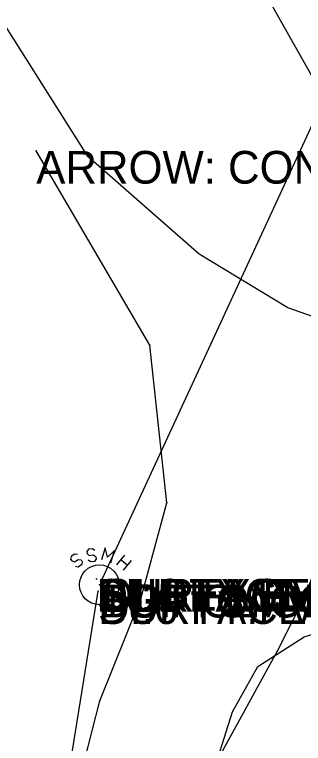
# Model space of a CAD drawing. Extents: x 997398 to 1003416, y 334596 to 337085.
# Drawn here: x 999242.3 to 999286.4, y 335737.9 to 335849.4 of the extents above; entities that cross this region are included whole.
import ezdxf

# ---------------------------------------------------------------- set-up
doc = ezdxf.new("R2010")
doc.units = 0
for name, color, linetype in [('S_CURB', 7, 'Continuous'), ('S_FIBER_OPTIC_CABLE', 7, 'Continuous'), ('S_FIBER_OPTIC_CABLE_ANNOT', 7, 'Continuous'), ('S_GRD_PT_SYM', 7, 'Continuous'), ('S_MANHOLE_ANNOT', 7, 'Continuous'), ('S_MISC_TOPO_POINT', 7, 'Continuous'), ('S_SANITARY_SEWER', 7, 'Continuous'), ('S_SANITARY_SEWER_ANNOT', 7, 'Continuous'), ('S_STREAM', 7, 'Continuous'), ('S_UTL_PT_SYM', 7, 'Continuous')]:
    doc.layers.add(name, color=color, linetype=linetype)

msp = doc.modelspace()

# ---------------------------------------------------------------- linework, layer by layer
at = {"layer": 'S_CURB'}
for points in [[(999309.27, 335795.7), (999307.46, 335796.33), (999284.06, 335804.54), (999270.5, 335812.71), (999253.53, 335827.61), (999240.32, 335848.52)], [(999266.19, 335714.69), (999272.09, 335731.57), (999275.58, 335742.68), (999279.48, 335749.62), (999286.56, 335754.18), (999294.45, 335756.63), (999296.19, 335756.83)]]:
    msp.add_lwpolyline(points, dxfattribs=at)
at = {"layer": 'S_FIBER_OPTIC_CABLE'}
for p, q in [((999262.96, 335798.83), (999245.57, 335828.53)), ((999265.55, 335774.66), (999262.96, 335798.83)), ((999261.59, 335759.99), (999265.55, 335774.66)), ((999282.47, 335752.03), (999294.24, 335775.36)), ((999255.29, 335744.38), (999261.59, 335759.99)), ((999268.37, 335726.35), (999282.47, 335752.03)), ((999251.87, 335731.03), (999255.29, 335744.38))]:
    msp.add_line(p, q, dxfattribs=at)
at = {"layer": 'S_GRD_PT_SYM'}
for points in [[(999254.8, 335763.03), (999254.8, 335763.08), (999254.8, 335763.03), (999254.75, 335763.03), (999254.8, 335763.03), (999254.8, 335762.98), (999254.8, 335763.03), (999254.85, 335763.03)], [(999255.64, 335763.04), (999255.64, 335763.09), (999255.64, 335763.04), (999255.59, 335763.04), (999255.64, 335763.04), (999255.64, 335762.99), (999255.64, 335763.04), (999255.69, 335763.04)], [(999255.03, 335761.15), (999255.03, 335761.2), (999255.03, 335761.15), (999254.98, 335761.15), (999255.03, 335761.15), (999255.03, 335761.1), (999255.03, 335761.15), (999255.08, 335761.15)]]:
    msp.add_lwpolyline(points, dxfattribs=at)
at = {"layer": 'S_SANITARY_SEWER'}
for p, q in [((999357.64, 335983.75), (999255.64, 335763.04)), ((999251.44, 335766.83), (999250.9, 335766.45)), ((999251.87, 335766.76), (999251.44, 335766.83)), ((999257.88, 335765.21), (999259.12, 335766.68)), ((999250.9, 335766.45), (999250.82, 335766.06)), ((999250.82, 335766.06), (999251.02, 335765.79)), ((999251.02, 335765.79), (999251.44, 335765.67)), ((999251.44, 335765.67), (999251.99, 335766.02)), ((999251.99, 335766.02), (999252.45, 335765.94)), ((999252.45, 335765.94), (999252.61, 335765.67)), ((999252.61, 335765.67), (999252.53, 335765.24)), ((999258.54, 335765.98), (999259.5, 335765.17)), ((999260.09, 335765.86), (999258.85, 335764.39)), ((999251.99, 335764.86), (999251.6, 335764.93)), ((999252.53, 335765.24), (999251.99, 335764.86)), ((999237.04, 335649.04), (999255.03, 335761.15))]:
    msp.add_line(p, q, dxfattribs=at)
for points in [[(999256.99, 335765.52), (999257.53, 335767.38), (999256.48, 335766.37), (999256.09, 335767.8), (999255.55, 335765.94)], [(999254.54, 335767.38), (999254.2, 335767.65), (999253.54, 335767.57), (999253.3, 335767.22), (999253.34, 335766.91), (999253.69, 335766.6), (999254.31, 335766.72), (999254.7, 335766.41), (999254.74, 335766.1), (999254.47, 335765.71), (999253.85, 335765.63), (999253.5, 335765.9)]]:
    msp.add_lwpolyline(points, dxfattribs=at)
msp.add_circle((999255.23, 335762.14), 3.05, dxfattribs=at)
at = {"layer": 'S_STREAM'}
msp.add_lwpolyline([(999258.36, 335906.71), (999263.07, 335891.05), (999267.78, 335875.39), (999279.06, 335855.39), (999290.34, 335835.39)], dxfattribs=at)
at = {"layer": 'S_UTL_PT_SYM'}
for points in [[(999245.57, 335828.53), (999245.57, 335828.58), (999245.57, 335828.53), (999245.52, 335828.53), (999245.57, 335828.53), (999245.57, 335828.48), (999245.57, 335828.53), (999245.62, 335828.53)], [(999262.96, 335798.83), (999262.96, 335798.88), (999262.96, 335798.83), (999262.91, 335798.83), (999262.96, 335798.83), (999262.96, 335798.78), (999262.96, 335798.83), (999263.01, 335798.83)], [(999265.55, 335774.66), (999265.55, 335774.71), (999265.55, 335774.66), (999265.5, 335774.66), (999265.55, 335774.66), (999265.55, 335774.61), (999265.55, 335774.66), (999265.6, 335774.66)], [(999254.8, 335763.03), (999254.8, 335763.08), (999254.8, 335763.03), (999254.75, 335763.03), (999254.8, 335763.03), (999254.8, 335762.98), (999254.8, 335763.03), (999254.85, 335763.03)], [(999255.23, 335762.14), (999255.23, 335762.19), (999255.23, 335762.14), (999255.18, 335762.14), (999255.23, 335762.14), (999255.23, 335762.09), (999255.23, 335762.14), (999255.28, 335762.14)], [(999255.64, 335763.04), (999255.64, 335763.09), (999255.64, 335763.04), (999255.59, 335763.04), (999255.64, 335763.04), (999255.64, 335762.99), (999255.64, 335763.04), (999255.69, 335763.04)], [(999255.03, 335761.15), (999255.03, 335761.2), (999255.03, 335761.15), (999254.98, 335761.15), (999255.03, 335761.15), (999255.03, 335761.1), (999255.03, 335761.15), (999255.08, 335761.15)], [(999261.59, 335759.99), (999261.59, 335760.04), (999261.59, 335759.99), (999261.54, 335759.99), (999261.59, 335759.99), (999261.59, 335759.94), (999261.59, 335759.99), (999261.64, 335759.99)], [(999282.47, 335752.03), (999282.47, 335752.08), (999282.47, 335752.03), (999282.42, 335752.03), (999282.47, 335752.03), (999282.47, 335751.98), (999282.47, 335752.03), (999282.52, 335752.03)], [(999255.29, 335744.38), (999255.29, 335744.43), (999255.29, 335744.38), (999255.24, 335744.38), (999255.29, 335744.38), (999255.29, 335744.33), (999255.29, 335744.38), (999255.34, 335744.38)]]:
    msp.add_lwpolyline(points, dxfattribs=at)

# ---------------------------------------------------------------- texts
at = {"layer": 'S_FIBER_OPTIC_CABLE_ANNOT'}
msp.add_text('ARROW: CONT NW', height=5, dxfattribs=at).set_placement((999245.57, 335823.53))
at = {"layer": 'S_MANHOLE_ANNOT'}
msp.add_text('BOTTOM OF MANHOLE', height=5, dxfattribs=at).set_placement((999255.23, 335757.14))
at = {"layer": 'S_MISC_TOPO_POINT'}
for p in [(999254.8, 335758.03), (999255.64, 335758.04), (999255.03, 335756.15)]:
    msp.add_text('SURFACE SHOT FOR UG PIPE', height=5, dxfattribs=at).set_placement(p)
at = {"layer": 'S_SANITARY_SEWER_ANNOT'}
for s, p in [('DI:4 TY:PVC TO NNW', (999254.8, 335758.03)), ('TOP CL OF MANHOLE', (999255.23, 335757.14)), ('DI:8 TY:PVC TO NNE', (999255.64, 335758.04)), ('DI:6 TY:PVC TO W.BY S.', (999255.03, 335756.15))]:
    msp.add_text(s, height=5, dxfattribs=at).set_placement(p)

doc.saveas('drawing.dxf')
